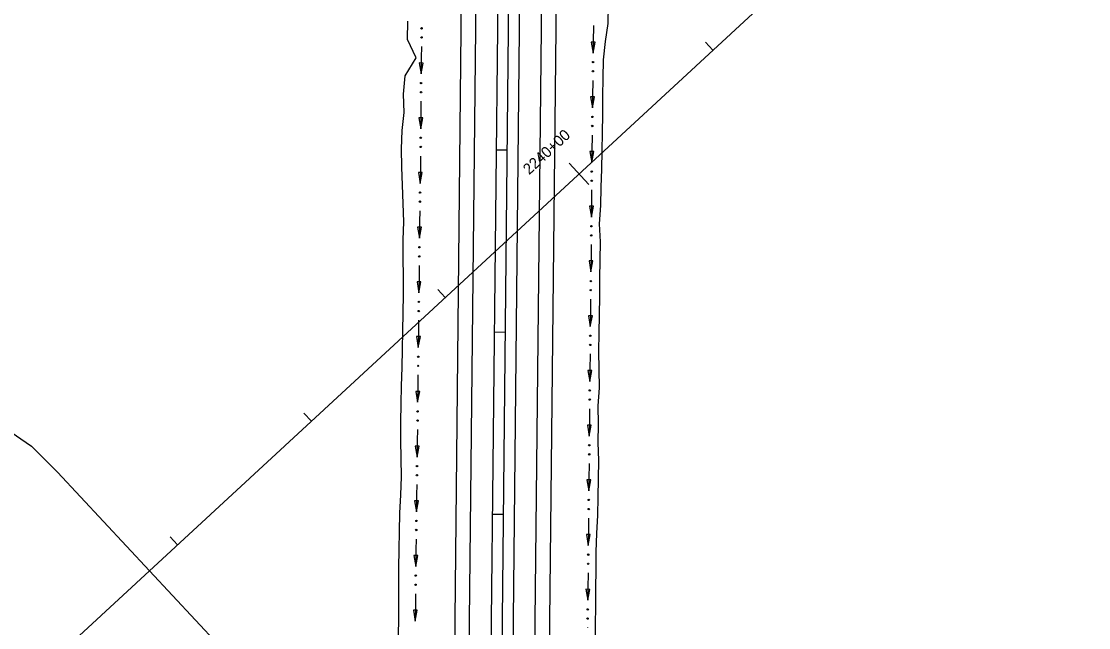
# Model space of a CAD drawing. Extents: x 1611108 to 1749517, y 619561 to 797725.
# Drawn here: x 1728056 to 1728642, y 772295 to 772627 of the extents above; entities that cross this region are included whole.
import ezdxf

# ---------------------------------------------------------------- set-up
doc = ezdxf.new("R2010")
doc.units = 0
for name, color, linetype in [('R_Ditch', 7, 'Continuous'), ('R_Horz Alg', 7, 'Continuous'), ('R_Horz Alg Stationing', 7, 'Continuous'), ('R_Horz Alg Stationing_Side Road', 7, 'Continuous'), ('R_Proposed Const Limits', 7, 'Continuous'), ('R_Proposed Road', 7, 'Continuous'), ('R_Striping', 7, 'Continuous')]:
    doc.layers.add(name, color=color, linetype=linetype)

msp = doc.modelspace()

# ---------------------------------------------------------------- linework, layer by layer
at = {"layer": 'R_Ditch'}
for p, q in [((1728370.83, 772615.91), (1728368.72, 772615.93)), ((1728368.72, 772615.93), (1728369.71, 772609.92)), ((1728369.71, 772609.92), (1728370.83, 772615.91)), ((1728276.47, 772604.42), (1728274.35, 772604.44)), ((1728274.35, 772604.44), (1728275.36, 772598.43)), ((1728275.36, 772598.43), (1728276.47, 772604.42)), ((1728370.46, 772585.87), (1728368.34, 772585.9)), ((1728368.34, 772585.9), (1728369.32, 772579.89)), ((1728369.32, 772579.89), (1728370.46, 772585.87)), ((1728276.25, 772574.39), (1728274.13, 772574.4)), ((1728274.13, 772574.4), (1728275.15, 772568.39)), ((1728275.15, 772568.39), (1728276.25, 772574.39)), ((1728370.06, 772555.84), (1728367.94, 772555.86)), ((1728367.94, 772555.86), (1728368.96, 772549.85)), ((1728368.96, 772549.85), (1728370.06, 772555.84)), ((1728275.95, 772544.34), (1728273.83, 772544.37)), ((1728273.83, 772544.37), (1728274.81, 772538.36)), ((1728274.81, 772538.36), (1728275.95, 772544.34)), ((1728369.84, 772525.81), (1728367.73, 772525.82)), ((1728367.73, 772525.82), (1728368.74, 772519.81)), ((1728368.74, 772519.81), (1728369.84, 772525.81)), ((1728275.55, 772514.31), (1728273.43, 772514.34)), ((1728273.43, 772514.34), (1728274.41, 772508.32)), ((1728274.41, 772508.32), (1728275.55, 772514.31)), ((1728369.59, 772495.77), (1728367.47, 772495.79)), ((1728367.47, 772495.79), (1728368.47, 772489.78)), ((1728368.47, 772489.78), (1728369.59, 772495.77)), ((1728275.23, 772484.27), (1728273.11, 772484.3)), ((1728273.11, 772484.3), (1728274.11, 772478.29)), ((1728274.11, 772478.29), (1728275.23, 772484.27)), ((1728369.27, 772465.73), (1728367.15, 772465.75)), ((1728367.15, 772465.75), (1728368.15, 772459.74)), ((1728368.15, 772459.74), (1728369.27, 772465.73)), ((1728274.92, 772454.24), (1728272.81, 772454.26)), ((1728272.81, 772454.26), (1728273.8, 772448.25)), ((1728273.8, 772448.25), (1728274.92, 772454.24)), ((1728368.98, 772435.7), (1728366.87, 772435.71)), ((1728366.87, 772435.71), (1728367.87, 772429.71)), ((1728367.87, 772429.71), (1728368.98, 772435.7)), ((1728274.58, 772424.2), (1728272.46, 772424.22)), ((1728272.46, 772424.22), (1728273.45, 772418.21)), ((1728273.45, 772418.21), (1728274.58, 772424.2)), ((1728368.71, 772405.66), (1728366.6, 772405.68)), ((1728366.6, 772405.68), (1728367.6, 772399.67)), ((1728367.6, 772399.67), (1728368.71, 772405.66)), ((1728274.23, 772394.16), (1728272.11, 772394.19)), ((1728272.11, 772394.19), (1728273.1, 772388.18)), ((1728273.1, 772388.18), (1728274.23, 772394.16)), ((1728368.44, 772375.62), (1728366.33, 772375.64)), ((1728366.33, 772375.64), (1728367.33, 772369.63)), ((1728367.33, 772369.63), (1728368.44, 772375.62)), ((1728273.88, 772364.13), (1728271.76, 772364.15)), ((1728271.76, 772364.15), (1728272.75, 772358.14)), ((1728272.75, 772358.14), (1728273.88, 772364.13)), ((1728368.17, 772345.58), (1728366.05, 772345.6)), ((1728366.05, 772345.6), (1728367.05, 772339.59)), ((1728367.05, 772339.59), (1728368.17, 772345.58)), ((1728273.54, 772334.09), (1728271.42, 772334.12)), ((1728271.42, 772334.12), (1728272.42, 772328.1)), ((1728272.42, 772328.1), (1728273.54, 772334.09)), ((1728367.88, 772315.55), (1728365.77, 772315.57)), ((1728365.77, 772315.57), (1728366.77, 772309.56)), ((1728366.77, 772309.56), (1728367.88, 772315.55)), ((1728273.21, 772304.06), (1728271.1, 772304.08)), ((1728271.1, 772304.08), (1728272.1, 772298.07)), ((1728272.1, 772298.07), (1728273.21, 772304.06))]:
    msp.add_line(p, q, dxfattribs=at)
for points in [[(1728369.87, 772624.92), (1728369.78, 772616.25), (1728369.71, 772609.92)], [(1728369.87, 772624.96), (1728369.87, 772624.92)], [(1728275.49, 772613.43), (1728275.43, 772607.24), (1728275.36, 772598.43)], [(1728275.49, 772613.47), (1728275.49, 772613.43)], [(1728369.52, 772594.89), (1728369.41, 772586.25), (1728369.32, 772579.89)], [(1728369.52, 772594.92), (1728369.52, 772594.89)], [(1728275.25, 772583.39), (1728275.21, 772577.24), (1728275.15, 772568.39)], [(1728275.25, 772583.43), (1728275.25, 772583.39)], [(1728369.12, 772564.85), (1728369.01, 772556.26), (1728368.96, 772549.85)], [(1728369.12, 772564.89), (1728369.12, 772564.85)], [(1728275.01, 772553.36), (1728274.93, 772547.24), (1728274.81, 772538.36)], [(1728275.01, 772553.39), (1728275.01, 772553.36)], [(1728368.85, 772534.81), (1728368.79, 772526.26), (1728368.74, 772519.81)], [(1728368.85, 772534.85), (1728368.85, 772534.81)], [(1728274.61, 772523.32), (1728274.53, 772517.24), (1728274.41, 772508.32)], [(1728274.61, 772523.36), (1728274.61, 772523.32)], [(1728368.63, 772504.78), (1728368.54, 772496.26), (1728368.47, 772489.78)], [(1728368.63, 772504.82), (1728368.63, 772504.78)], [(1728274.26, 772493.28), (1728274.2, 772487.25), (1728274.11, 772478.29)], [(1728274.26, 772493.32), (1728274.26, 772493.28)], [(1728368.31, 772474.74), (1728368.22, 772466.26), (1728368.15, 772459.74)], [(1728368.31, 772474.78), (1728368.31, 772474.74)], [(1728273.96, 772463.25), (1728273.9, 772457.25), (1728273.8, 772448.25)], [(1728273.96, 772463.29), (1728273.96, 772463.25)], [(1728368.01, 772444.7), (1728367.93, 772436.26), (1728367.87, 772429.71)], [(1728368.01, 772444.74), (1728368.01, 772444.7)], [(1728273.62, 772433.21), (1728273.55, 772427.25), (1728273.45, 772418.21)], [(1728273.62, 772433.25), (1728273.62, 772433.21)], [(1728367.74, 772414.67), (1728367.66, 772406.26), (1728367.6, 772399.67)], [(1728367.74, 772414.71), (1728367.74, 772414.67)], [(1728273.27, 772403.18), (1728273.2, 772397.25), (1728273.1, 772388.18)], [(1728273.27, 772403.21), (1728273.27, 772403.18)], [(1728367.47, 772384.63), (1728367.39, 772376.26), (1728367.33, 772369.63)], [(1728367.47, 772384.67), (1728367.47, 772384.63)], [(1728272.92, 772373.14), (1728272.86, 772367.25), (1728272.75, 772358.14)], [(1728272.92, 772373.18), (1728272.92, 772373.14)], [(1728367.19, 772354.59), (1728367.12, 772346.27), (1728367.05, 772339.59)], [(1728367.19, 772354.63), (1728367.19, 772354.59)], [(1728272.58, 772343.1), (1728272.52, 772337.26), (1728272.42, 772328.1)], [(1728272.58, 772343.14), (1728272.58, 772343.1)], [(1728366.91, 772324.56), (1728366.83, 772316.27), (1728366.77, 772309.56)], [(1728366.91, 772324.6), (1728366.91, 772324.56)], [(1728272.25, 772313.07), (1728272.18, 772307.26), (1728272.1, 772298.07)], [(1728272.25, 772313.11), (1728272.25, 772313.07)], [(1728366.6, 772294.56), (1728366.6, 772294.52)]]:
    msp.add_lwpolyline(points, dxfattribs=at)
for centre in [(1728275.62, 772623.46), (1728275.58, 772618.45), (1728369.69, 772604.92), (1728369.62, 772599.91), (1728275.36, 772593.42), (1728275.33, 772588.41), (1728369.29, 772574.88), (1728369.22, 772569.87), (1728275.15, 772563.39), (1728275.11, 772558.38), (1728368.96, 772544.85), (1728368.92, 772539.84), (1728274.78, 772533.35), (1728274.72, 772528.34), (1728368.7, 772509.8), (1728368.74, 772514.81), (1728274.34, 772498.31), (1728274.39, 772503.32), (1728368.45, 772484.77), (1728368.4, 772479.76), (1728274.1, 772473.28), (1728274.05, 772468.27), (1728368.13, 772454.74), (1728368.09, 772449.73), (1728273.77, 772443.24), (1728273.72, 772438.23), (1728367.86, 772424.7), (1728367.82, 772419.69), (1728273.43, 772413.21), (1728273.37, 772408.2), (1728367.59, 772394.66), (1728367.55, 772389.65), (1728273.08, 772383.17), (1728273.02, 772378.16), (1728367.32, 772364.63), (1728367.28, 772359.62), (1728272.73, 772353.13), (1728272.67, 772348.13), (1728367.04, 772334.59), (1728366.99, 772329.58), (1728272.4, 772323.1), (1728272.34, 772318.09), (1728366.75, 772304.55), (1728366.69, 772299.54)]:
    msp.add_circle(centre, 0.375, dxfattribs=at)
at = {"layer": 'R_Horz Alg'}
for p, q in [((1726122.78, 770473.69), (1737235.67, 780746.34)), ((1728306.95, 771056.83), (1728332.15, 773463.77))]:
    msp.add_line(p, q, dxfattribs=at)
at = {"layer": 'R_Horz Alg Stationing'}
for points in [[(1728431.35, 772615.88), (1728435.42, 772611.47)], [(1728356.56, 772549.47), (1728367.42, 772537.72)], [(1728284.48, 772480.12), (1728288.56, 772475.71)], [(1728211.05, 772412.24), (1728215.13, 772407.83)], [(1728137.62, 772344.36), (1728141.69, 772339.95)]]:
    msp.add_lwpolyline(points, dxfattribs=at)
at = {"layer": 'R_Horz Alg Stationing_Side Road'}
for points in [[(1728316.65, 772556.81), (1728322.65, 772556.74)], [(1728315.61, 772456.81), (1728321.61, 772456.75)], [(1728314.56, 772356.82), (1728320.56, 772356.75)]]:
    msp.add_lwpolyline(points, dxfattribs=at)
at = {"layer": 'R_Proposed Const Limits'}
for points in [[(1728370.98, 772286.22), (1728371.06, 772296.22), (1728371.13, 772306.22), (1728371.26, 772316.22), (1728371.3, 772326.22), (1728371.45, 772336.22), (1728371.78, 772346.22), (1728372.28, 772356.21), (1728372.54, 772366.21), (1728372.68, 772376.21), (1728372.83, 772386.21), (1728372.43, 772396.21), (1728372.66, 772406.21), (1728372.55, 772416.21), (1728373.14, 772426.21), (1728373.04, 772436.21), (1728372.75, 772446.21), (1728373.07, 772456.21), (1728373.27, 772466.21), (1728373.38, 772476.21), (1728373.43, 772486.21), (1728373.57, 772496.21), (1728373.74, 772506.2), (1728373.29, 772516.21), (1728373.88, 772526.2), (1728374.09, 772536.2), (1728374.39, 772546.2), (1728374.58, 772556.2), (1728374.79, 772566.2), (1728375, 772576.2), (1728374.98, 772586.2), (1728375.17, 772596.19), (1728375.35, 772606.19), (1728376.44, 772616.18), (1728377.88, 772626.17), (1728378.2, 772636.17)], [(1728262.81, 772287.35), (1728263.1, 772297.35), (1728263.07, 772307.35), (1728263.07, 772317.35), (1728263.21, 772327.35), (1728263.37, 772337.35), (1728263.54, 772347.35), (1728263.75, 772357.35), (1728264.25, 772367.34), (1728264.52, 772377.34), (1728264.35, 772387.34), (1728264.18, 772397.35), (1728264.23, 772407.35), (1728264.45, 772417.34), (1728264.66, 772427.34), (1728264.87, 772437.34), (1728265.09, 772447.34), (1728265.3, 772457.34), (1728265.49, 772467.34), (1728265.68, 772477.34), (1728265.63, 772487.34), (1728265.51, 772497.34), (1728265.52, 772507.34), (1728265.81, 772517.34), (1728265.51, 772527.34), (1728265.09, 772537.34), (1728264.74, 772547.35), (1728264.58, 772557.35), (1728264.95, 772567.35), (1728266.05, 772577.34), (1728265.75, 772587.34), (1728266.51, 772597.33), (1728272.71, 772607.27), (1728267.8, 772617.32), (1728268.01, 772627.32)], [(1727975.2, 772404.26), (1728005.73, 772416.83), (1728029.28, 772414.02), (1728047.45, 772403.84), (1728061.62, 772394.06), (1728075.84, 772379.85), (1728176.79, 772271.62), (1728196.21, 772249.33), (1728201.8, 772239.35), (1728206.79, 772219.99), (1728207, 772200.23), (1728202.16, 772184.59)]]:
    msp.add_lwpolyline(points, dxfattribs=at)
at = {"layer": 'R_Proposed Road'}
for p, q in [((1728331.96, 771726.6), (1728348.3, 773286.51)), ((1728339.96, 771726.37), (1728356.3, 773286.58)), ((1728289.96, 771917.47), (1728301.76, 773044.77)), ((1728297.97, 771918.9), (1728309.72, 773040.48))]:
    msp.add_line(p, q, dxfattribs=at)
at = {"layer": 'R_Striping'}
for p, q in [((1728310.3, 771950.35), (1728321.72, 773040.36)), ((1728322.3, 771950.23), (1728331.17, 772796.67))]:
    msp.add_line(p, q, dxfattribs=at)

# ---------------------------------------------------------------- texts
at = {"layer": 'R_Horz Alg Stationing'}
msp.add_text('2240+00', height=6, rotation=42.75, dxfattribs=at).set_placement((1728334.61, 772542.8))

doc.saveas('drawing.dxf')
